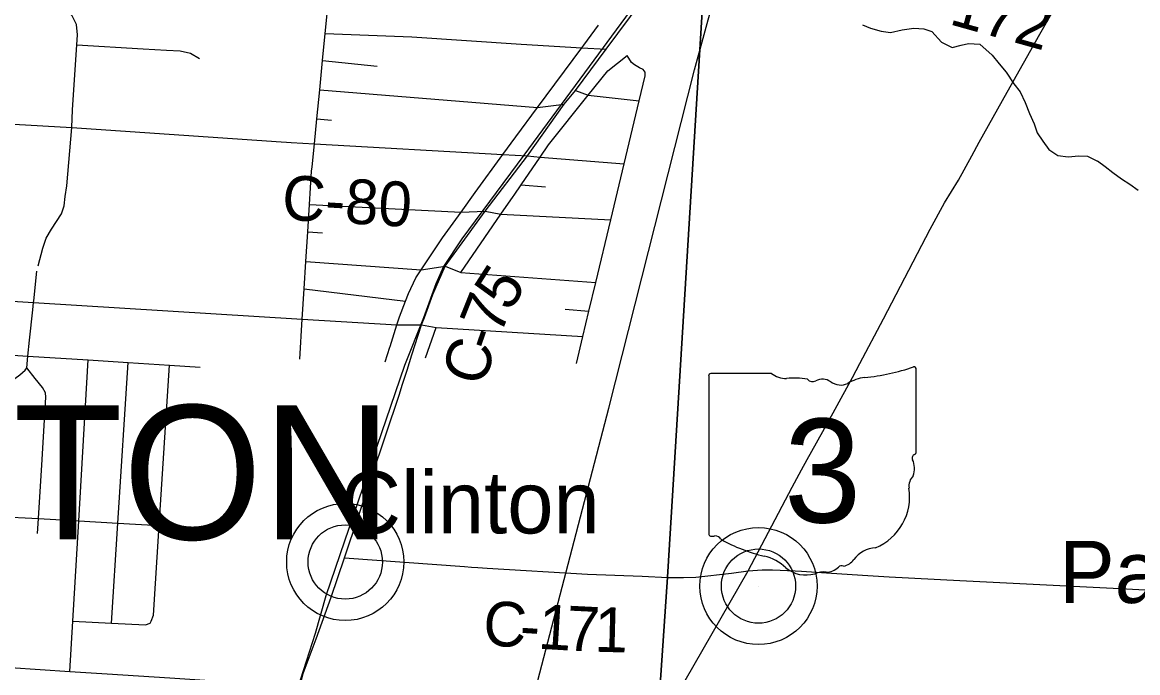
# Model space of a CAD drawing. Extents: x 0 to 34, y 0 to 22.
# Drawn here: x 2.735 to 4.152, y 14.745 to 15.572 of the extents above; entities that cross this region are included whole.
import ezdxf

# ---------------------------------------------------------------- set-up
doc = ezdxf.new("R2010")
doc.units = 0
for name, color, linetype in [('GM_X_City_Street', 7, 'Continuous'), ('GM_X_County_Road', 7, 'Continuous'), ('GM_X_County_Road_Text', 7, 'Continuous'), ('GM_X_Minor_River', 7, 'Continuous'), ('GM_X_Rail_Line', 7, 'Continuous'), ('GM_X_State_Location', 7, 'Continuous'), ('GM_X_State_Route', 7, 'Continuous'), ('GM_X_State_Shield', 7, 'Continuous'), ('GM_X_Township_Road', 7, 'Continuous'), ('GM_X_Township_Text', 7, 'Continuous'), ('GM_X_Unincorporated', 7, 'Continuous'), ('GM_X_Unincorporated_Location', 7, 'Continuous'), ('GM_X_Unincorporated_Text', 7, 'Continuous')]:
    doc.layers.add(name, color=color, linetype=linetype)

msp = doc.modelspace()

# ---------------------------------------------------------------- linework, layer by layer
at = {"layer": 'GM_X_City_Street'}
for points in [[(2.7548, 15.2621), (2.761, 15.2846), (2.7651, 15.2972), (2.7718, 15.3086), (2.7845, 15.3283), (2.7879, 15.3384), (2.7892, 15.3501), (2.7914, 15.3638), (2.7977, 15.4379), (2.7984, 15.4602), (2.804, 15.543), (2.8049, 15.5558), (2.8035, 15.569), (2.7979, 15.5809), (2.791, 15.5893), (2.7832, 15.6015), (2.782, 15.6085)], [(2.804, 15.543), (2.8883, 15.5381), (2.918, 15.5362), (2.9355, 15.5352), (2.9485, 15.5325), (2.96, 15.5257)], [(2.4807, 15.1592), (2.4837, 15.1618), (2.4924, 15.1633), (2.5248, 15.1613), (2.5675, 15.1586), (2.6134, 15.1556), (2.6646, 15.1524), (2.7419, 15.1474), (2.8183, 15.1426), (2.8695, 15.1393), (2.9219, 15.136), (2.9607, 15.1335)], [(2.6932, 14.753), (2.6975, 14.844), (2.7036, 14.9438), (2.7132, 15.1014), (2.7144, 15.107), (2.7189, 15.1143), (2.7315, 15.1237), (2.7383, 15.1294), (2.7404, 15.1326), (2.7419, 15.1474), (2.744, 15.1677)], [(2.7954, 14.7466), (2.7991, 14.8106), (2.8065, 14.938), (2.8183, 15.1426)], [(2.8482, 14.8081), (2.8564, 14.9351), (2.8695, 15.1393)], [(2.8971, 14.8082), (2.8986, 14.8105), (2.9013, 14.8181), (2.9087, 14.9322), (2.9219, 15.136)], [(2.7541, 14.9218), (2.7553, 14.9409), (2.7599, 15.0159), (2.7649, 15.0953), (2.7641, 15.1006), (2.7607, 15.1074), (2.7512, 15.1188), (2.7404, 15.1326)], [(2.4595, 14.9576), (2.5072, 14.9549), (2.5093, 14.9548), (2.5526, 14.9524), (2.555, 14.9522), (2.603, 14.9495), (2.6541, 14.9466), (2.7036, 14.9438), (2.7553, 14.9409), (2.8065, 14.938), (2.8564, 14.9351), (2.9087, 14.9322), (2.9465, 14.93)], [(2.7991, 14.8106), (2.8482, 14.8081), (2.8914, 14.8059), (2.8971, 14.8082)]]:
    msp.add_lwpolyline(points, dxfattribs=at)
at = {"layer": 'GM_X_County_Road'}
for p, q in [((3.4375, 15.4849), (3.4766, 15.5374)), ((3.4232, 15.4678), (3.4375, 15.4849)), ((3.2238, 15.1297), (3.2299, 15.1489)), ((3.2176, 15.1106), (3.2238, 15.1297))]:
    msp.add_line(p, q, dxfattribs=at)
msp.add_lwpolyline([(2.1, 16.5143), (2.1, 14.1), (3.5033, 14.1), (3.5067, 14.1788), (3.5412, 14.6736), (3.5547, 14.8664), (3.6065, 15.7173), (3.6083, 15.7281), (3.6105, 15.7435), (3.6146, 15.8068), (3.6204, 15.8961), (3.634, 16.1053), (3.6418, 16.2257), (3.654, 16.4154), (3.6172, 16.4188), (3.4065, 16.4352), (3.1867, 16.4496), (3.1585, 16.4507), (3.0788, 16.4569), (2.884, 16.4676), (2.7034, 16.4752), (2.5328, 16.4826), (2.3641, 16.4932), (2.2435, 16.5033)], close=True, dxfattribs=at)
for points in [[(5.4989, 16.2977), (5.2615, 16.3089), (5.0301, 16.3238), (4.7825, 16.3404), (4.4809, 16.3594), (4.0961, 16.3837), (3.9805, 16.3916), (3.8512, 16.4005), (3.654, 16.4154), (3.6418, 16.2257), (3.634, 16.1053), (3.6204, 15.8961), (3.6146, 15.8068), (3.6105, 15.7435), (3.6083, 15.7281), (3.6065, 15.7173), (3.5547, 14.8664), (3.5412, 14.6736), (3.5067, 14.1788), (3.5033, 14.1), (8.2619, 14.1)], [(3.4766, 15.5374), (3.5224, 15.599), (3.5801, 15.6767), (3.5879, 15.6873), (3.6067, 15.7167), (3.6085, 15.7276), (3.6107, 15.7429), (3.6148, 15.8062), (3.6168, 15.836)], [(2.3732, 15.4628), (2.4656, 15.4571), (2.7977, 15.4379), (3.0635, 15.4196), (3.0705, 15.4192), (3.0764, 15.4188)], [(3.2456, 15.1967), (3.2563, 15.2256), (3.2721, 15.2619), (3.287, 15.2819), (3.3228, 15.3316), (3.3767, 15.4018), (3.4232, 15.4678)], [(3.0764, 15.4188), (3.1059, 15.4172), (3.3455, 15.4036), (3.3767, 15.4018)], [(3.2299, 15.1489), (3.2421, 15.1873), (3.2456, 15.1967)], [(3.0621, 14.4992), (3.0635, 14.5192), (3.0677, 14.5689), (3.0677, 14.5764), (3.0735, 14.6423), (3.0765, 14.6649), (3.0818, 14.698), (3.0887, 14.7325), (3.0915, 14.7442), (3.1083, 14.7882), (3.1272, 14.8409), (3.1443, 14.8912), (3.214, 15.099), (3.2176, 15.1106)], [(3.1443, 14.8912), (3.2965, 14.8799), (3.3055, 14.8793)], [(3.3055, 14.8793), (3.3134, 14.8788), (3.3254, 14.8781)], [(3.3254, 14.8781), (3.4527, 14.8703), (3.5224, 14.8677), (3.5549, 14.8659), (3.5569, 14.8659)], [(3.5569, 14.8659), (3.5747, 14.8659), (3.5906, 14.8663), (3.6357, 14.8714), (3.6569, 14.8747), (3.6748, 14.876), (3.6879, 14.876), (3.7167, 14.8746)], [(3.7167, 14.8746), (3.7246, 14.8742), (3.7564, 14.8721)], [(3.7564, 14.8721), (3.8022, 14.869), (3.8359, 14.8671)], [(3.8359, 14.8671), (3.926, 14.8621), (4.1376, 14.8515), (4.3005, 14.8428), (4.4125, 14.8367), (4.4323, 14.8358)]]:
    msp.add_lwpolyline(points, dxfattribs=at)
at = {"layer": 'GM_X_Minor_River'}
for points in [[(3.8024, 15.5683), (3.8126, 15.5644), (3.8258, 15.5605), (3.8376, 15.5585), (3.8528, 15.5621), (3.8676, 15.5642), (3.8801, 15.5634), (3.8904, 15.5598), (3.9024, 15.5464), (3.916, 15.5395), (3.9274, 15.5424), (3.9369, 15.5446), (3.9513, 15.5437), (3.9671, 15.5298), (3.9757, 15.5188), (3.9847, 15.5084), (3.9944, 15.4935), (4.0027, 15.4832), (4.009, 15.4698), (4.0146, 15.4557), (4.0205, 15.4428), (4.0242, 15.4313), (4.0313, 15.4206), (4.0388, 15.4099), (4.0505, 15.4022), (4.0634, 15.4006), (4.077, 15.402), (4.088, 15.4015), (4.1009, 15.395)], [(4.1523, 15.358), (4.1418, 15.3657), (4.1312, 15.3722), (4.1203, 15.3803), (4.1105, 15.388), (4.1009, 15.395)]]:
    msp.add_lwpolyline(points, dxfattribs=at)
at = {"layer": 'GM_X_Rail_Line'}
for points in [[(3.7202, 17.4495), (3.6121, 15.7571), (3.5991, 15.7141), (3.5781, 15.6833), (3.3718, 15.4026), (3.2933, 15.2964), (3.27, 15.2612), (3.26, 15.2394), (3.2447, 15.1962), (3.2204, 15.1356), (3.1206, 14.8429), (3.107, 14.7951), (3.0878, 14.7358), (3.0717, 14.6527), (3.0679, 14.583), (3.0599, 14.4798), (3.0531, 14.3964), (3.0341, 14.1)], [(3.2263, 14.1), (3.3201, 14.4671), (3.4798, 15.0811), (3.5889, 15.5111), (3.6244, 15.6418), (3.9439, 16.2089), (4.0935, 16.4703), (4.1354, 16.5172), (4.1886, 16.568), (4.5538, 16.8382), (4.6413, 16.9169), (4.6831, 16.9702), (4.73, 17.0374), (4.7604, 17.097), (4.7896, 17.177), (4.8023, 17.2505), (4.8213, 17.366)]]:
    msp.add_lwpolyline(points, dxfattribs=at)
at = {"layer": 'GM_X_State_Route'}
for p, q in [((3.6569, 14.8747), (3.713, 14.9807)), ((3.5769, 14.7351), (3.6569, 14.8747))]:
    msp.add_line(p, q, dxfattribs=at)
for points in [[(3.9411, 15.4018), (3.9506, 15.4193), (3.9861, 15.4829), (4.0275, 15.5564), (4.0681, 15.6282)], [(3.7989, 15.1379), (3.8291, 15.1946), (3.8884, 15.3089), (3.9064, 15.3422), (3.9244, 15.3712), (3.9411, 15.4018)], [(3.7847, 15.1116), (3.7895, 15.1202), (3.7989, 15.1379)], [(3.7319, 15.0159), (3.7576, 15.0623), (3.7847, 15.1116)], [(3.713, 14.9807), (3.7246, 15.0028), (3.7319, 15.0159)]]:
    msp.add_lwpolyline(points, dxfattribs=at)
at = {"layer": 'GM_X_State_Shield'}
for p, q in [((3.6068, 15.122), (3.6068, 14.9219)), ((3.6866, 15.1255), (3.6094, 15.1255)), ((3.8705, 15.0258), (3.8705, 15.1304)), ((3.8704, 15.0258), (3.8705, 15.0258))]:
    msp.add_line(p, q, dxfattribs=at)
for centre, radius, start, end in [((3.7766, 15.3983), 0.2796, 275.8445, 288.9065), ((3.8675, 15.1309), 0.00294, 351.8621, 97.738), ((3.6098, 15.1225), 0.00305, 98.1301, 188.1301), ((3.705, 15.1487), 0.0296, 231.6195, 271.1119), ((3.7148, 15.0131), 0.1064, 80.4867, 94.9883), ((3.8122, 15.0644), 0.0563, 97.3462, 120.7689), ((3.739, 15.1235), 0.00855, 219.7921, 297.1024), ((3.7515, 15.1004), 0.0178, 54.4667, 119.1411), ((3.7745, 15.1321), 0.0214, 233.8562, 294.8282), ((3.8698, 15.0181), 0.00454, 107.944, 210.337), ((3.8673, 15.0254), 0.00314, 289.6038, 7.7341), ((3.8409, 15.0048), 0.0273, 340.033, 23.6496), ((3.881, 14.9819), 0.0198, 136.8065, 186.9296), ((3.7922, 14.9686), 0.0699, 292.3089, 8.9858), ((3.6099, 14.9215), 0.00308, 171.9584, 258.3066), ((3.6103, 14.942), 0.0235, 267.339, 280.6039), ((3.6151, 14.9104), 0.00848, 29.7484, 93.2717), ((3.7222, 15.0902), 0.2019, 240.4129, 257.1985), ((3.662, 14.832), 0.0632, 47.1842, 75.836), ((3.8217, 14.8657), 0.0383, 94.4031, 142.5768), ((3.7564, 14.8944), 0.0214, 268.777, 315.5493), ((3.7757, 14.875), 0.00601, 65.7517, 132.6484), ((3.7732, 14.9025), 0.0226, 282.8732, 323.2771), ((3.7303, 14.9094), 0.0401, 230.7004, 286.2918), ((3.7535, 14.8402), 0.0329, 85.6951, 111.2099)]:
    msp.add_arc(centre, radius, start, end, dxfattribs=at)
at = {"layer": 'GM_X_Township_Road'}
for p, q in [((3.1164, 15.523), (3.1857, 15.5157)), ((3.4232, 15.4678), (3.4375, 15.4849)), ((3.109, 15.449), (3.1275, 15.4473)), ((3.3684, 15.3649), (3.3996, 15.3627)), ((3.0975, 15.3053), (3.116, 15.3039)), ((3.0929, 15.233), (3.2217, 15.2173)), ((2.744, 15.1677), (2.7481, 15.2061)), ((3.4247, 15.2073), (3.4546, 15.2044)), ((3.2469, 15.1451), (3.2607, 15.1839)), ((3.1959, 15.14), (3.2019, 15.1588))]:
    msp.add_line(p, q, dxfattribs=at)
for points in [[(3.103, 15.3881), (3.1059, 15.4172), (3.109, 15.449), (3.1127, 15.486), (3.1164, 15.523), (3.1198, 15.5574), (3.1231, 15.5909), (3.1277, 15.6365), (3.1325, 15.7086), (3.1347, 15.7399), (3.1368, 15.7707), (3.1371, 15.7755), (3.137, 15.7819)], [(3.4457, 15.5393), (3.4482, 15.5428), (3.4668, 15.5678)], [(3.1198, 15.5574), (3.2295, 15.5532), (3.3688, 15.544), (3.4457, 15.5393), (3.4766, 15.5374)], [(3.2019, 15.1588), (3.2022, 15.1597), (3.2108, 15.187), (3.2141, 15.1972), (3.2217, 15.2173), (3.2255, 15.2271), (3.2348, 15.2471), (3.2415, 15.2571), (3.2484, 15.2674), (3.2685, 15.2979), (3.2922, 15.3303), (3.3103, 15.3552), (3.3455, 15.4036), (3.3617, 15.4259), (3.3894, 15.4633), (3.4457, 15.5393)], [(3.3584, 15.3504), (3.3595, 15.3519), (3.3684, 15.3649), (3.3927, 15.4004), (3.4034, 15.4159), (3.4538, 15.4789), (3.4786, 15.5099), (3.5032, 15.5293)], [(3.4387, 15.138), (3.4469, 15.1723), (3.4546, 15.2044), (3.4633, 15.2411), (3.4823, 15.3207), (3.4993, 15.3917), (3.5185, 15.472), (3.526, 15.5035), (3.5261, 15.5081), (3.5235, 15.5116), (3.519, 15.5139), (3.5125, 15.5178), (3.5088, 15.5205), (3.5032, 15.5293)], [(3.1127, 15.486), (3.3894, 15.4633), (3.4232, 15.4678)], [(3.4375, 15.4849), (3.4538, 15.4789), (3.5185, 15.472)], [(3.3767, 15.4018), (3.3927, 15.4004), (3.4993, 15.3917)], [(3.0873, 15.1434), (3.0905, 15.1944), (3.0929, 15.233), (3.0951, 15.2677), (3.0975, 15.3053), (3.0997, 15.3401), (3.1024, 15.3823), (3.103, 15.3881)], [(3.2919, 15.2535), (3.3429, 15.3277), (3.3584, 15.3504)], [(3.0997, 15.3401), (3.2922, 15.3303), (3.3228, 15.3316), (3.3429, 15.3277), (3.4823, 15.3207)], [(3.0951, 15.2677), (3.2415, 15.2571), (3.2721, 15.2619), (3.2919, 15.2535), (3.4633, 15.2411)], [(2.7481, 15.2061), (2.7492, 15.2157), (2.7494, 15.2178), (2.7535, 15.2554)], [(2.5506, 15.228), (2.7492, 15.2157), (3.0905, 15.1944), (3.2108, 15.187), (3.2421, 15.1873), (3.2514, 15.1856)], [(3.2514, 15.1856), (3.2607, 15.1839), (3.4469, 15.1723)], [(2.6849, 14.7535), (2.6932, 14.753), (2.7199, 14.7515), (2.7954, 14.7466), (2.8426, 14.7436), (2.9224, 14.7384), (3.0367, 14.731), (3.0887, 14.7325)]]:
    msp.add_lwpolyline(points, dxfattribs=at)
at = {"layer": 'GM_X_Unincorporated'}
for centre, radius in [((3.1451, 14.8858), 0.0744), ((3.1451, 14.8858), 0.0472), ((3.6701, 14.8552), 0.0744), ((3.6701, 14.8552), 0.0472)]:
    msp.add_circle(centre, radius, dxfattribs=at)
at = {"layer": 'GM_X_Unincorporated_Location'}
for p, q in [((3.1451, 14.8858), (3.1451, 14.8858)), ((3.6701, 14.8552), (3.6701, 14.8552))]:
    msp.add_line(p, q, dxfattribs=at)

# ---------------------------------------------------------------- texts
at = {"layer": 'GM_X_County_Road_Text'}
for s, height, rotation, p in [('C-172', 0.05682, 344.3586, (3.8337, 15.5913)), ('C-80', 0.05682, 356.612, (3.0636, 15.3211)), ('5', 0.0568, 57.3189, (3.3536, 15.2023)), ('7', 0.0568, 68.1039, (3.3419, 15.1723)), ('-', 0.0568, 70.7405, (3.3344, 15.1509)), ('C', 0.0568, 72.5018, (3.3205, 15.1069)), ('C', 0.0568, 356.2661, (3.319, 14.7803)), ('1', 0.0568, 356.5847, (3.3892, 14.7757)), ('7', 0.0568, 357.1405, (3.4248, 14.7736)), ('1', 0.0568, 358.5617, (3.4613, 14.7718)), ('-', 0.0568, 356.3489, (3.3657, 14.7772))]:
    msp.add_text(s, height=height, rotation=rotation, dxfattribs=at).set_placement(p)
at = {"layer": 'GM_X_State_Location'}
for s in ['s', 'r']:
    msp.add_text(s, height=0.000189, dxfattribs=at).set_placement((3.7357, 15.0087))
msp.add_text('3', height=0.000189, rotation=0, dxfattribs=at).set_placement((3.7071, 14.9949))
at = {"layer": 'GM_X_State_Shield'}
msp.add_text('3', height=0.1318, dxfattribs=at).set_placement((3.7025, 14.936))
at = {"layer": 'GM_X_Township_Text'}
msp.add_text('CLINTON', height=0.17045, rotation=0, dxfattribs=at).set_placement((2.2039, 14.9145))
at = {"layer": 'GM_X_Unincorporated_Text'}
for s, height, p in [('Clinton', 0.07898, (3.1396, 14.9221)), ('Parks Mills', 0.078977, (4.0521, 14.8337))]:
    msp.add_text(s, height=height, rotation=0, dxfattribs=at).set_placement(p)

doc.saveas('drawing.dxf')
